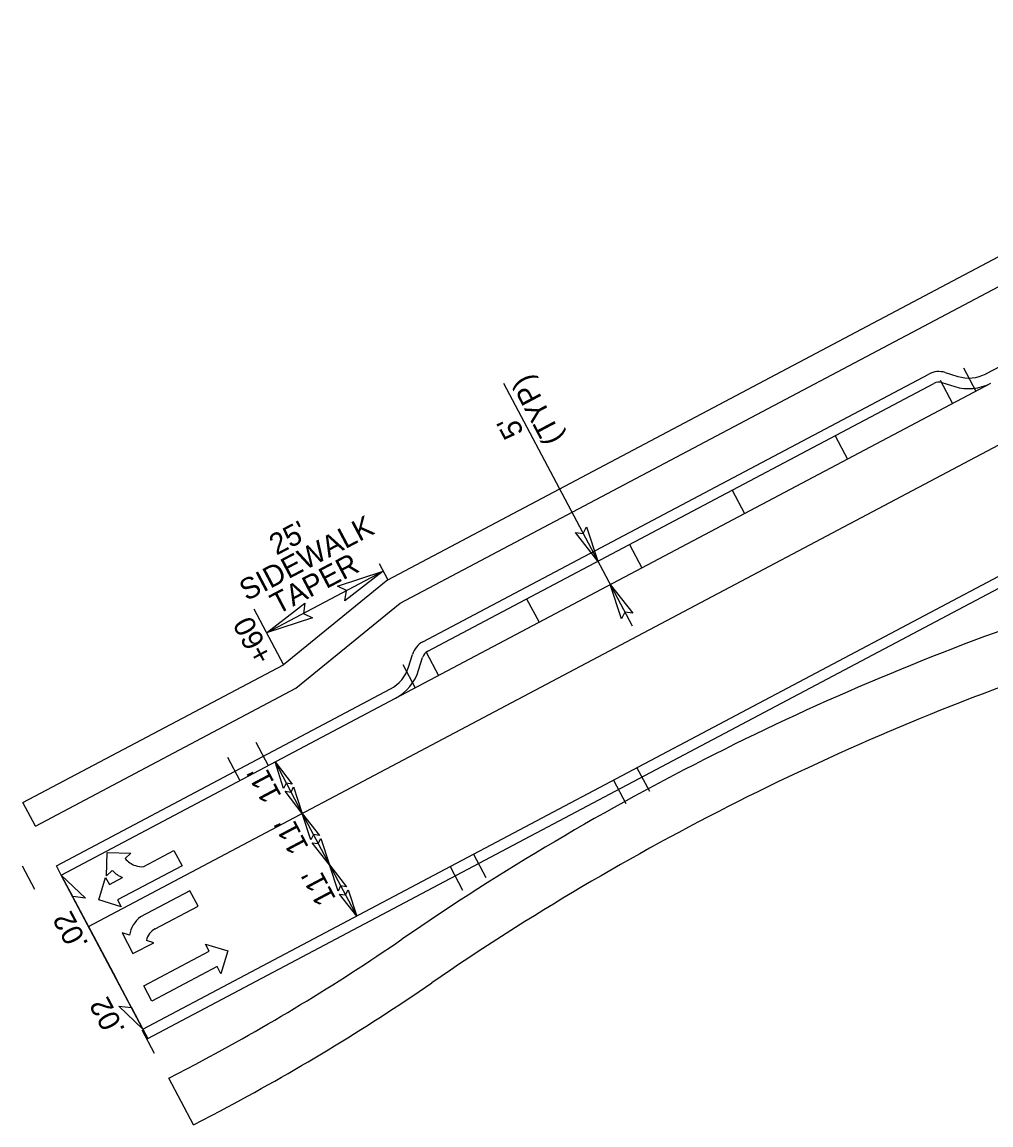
# Model space of a CAD drawing. Extents: x 1486489 to 1490134, y 497089 to 500876.
# Drawn here: x 1487826.7 to 1488009.9, y 498365 to 498573.7 of the extents above; entities that cross this region are included whole.
import ezdxf

# ---------------------------------------------------------------- set-up
doc = ezdxf.new("R2010")
doc.units = 0
for name, color, linetype in [('DEV PRELIMINARY STAMP CELL', 7, 'Continuous'), ('Gray Area Fill Shapes', 7, 'Continuous'), ('Prop Horizontal Alignment Station Label', 7, 'Continuous'), ('Scratch_Level_5', 7, 'Continuous'), ('Sheet Block Title CELL', 7, 'Continuous'), ('Sheet Border Standard 30in CELL', 7, 'Continuous'), ('Sheet Cutting Line CELL', 7, 'Continuous'), ('Sheet Plot Border Inside CELL', 7, 'Continuous'), ('Sheet Plot Border Outside CELL', 7, 'Continuous'), ('Sheet Sticker Exception Certification CELL', 7, 'Continuous'), ('Sheet Title CELL', 7, 'Continuous')]:
    doc.layers.add(name, color=color, linetype=linetype)

msp = doc.modelspace()

# ---------------------------------------------------------------- linework, layer by layer
at = {"layer": 'DEV PRELIMINARY STAMP CELL'}
for p in [(1487834.08, 498412.33), (1487849.52, 498383.17)]:
    msp.add_line(p, (1487844.38, 498392.89), dxfattribs=at)
for points in [[(1487834.08, 498412.33), (1487838.66, 498407.97), (1487836.25, 498408.25)], [(1487849.52, 498383.17), (1487844.95, 498387.53), (1487847.36, 498387.25)]]:
    msp.add_lwpolyline(points, close=True, dxfattribs=at)
at = {"layer": 'Prop Horizontal Alignment Station Label'}
for p, q in [((1487895.85, 498468.22), (1488095.16, 498573.73)), ((1487898.19, 498463.8), (1488097.5, 498569.31)), ((1487895.85, 498468.22), (1487876.09, 498452.11)), ((1487878.43, 498447.69), (1487898.19, 498463.8)), ((1487826.83, 498426.03), (1487876.09, 498452.11)), ((1487829.17, 498421.61), (1487878.43, 498447.69)), ((1487829.17, 498421.61), (1487826.83, 498426.03)), ((1487854.44, 498373.89), (1487859.51, 498376.57)), ((1487859.11, 498365.05), (1487854.44, 498373.89)), ((1487859.11, 498365.05), (1487864.18, 498367.73))]:
    msp.add_line(p, q, dxfattribs=at)
for centre, radius, start, end in [((1488184.66, 497984.09), 505, 108.9278, 124.5146), ((1488184.66, 497984.09), 495, 108.9278, 124.5146), ((1487674.7, 498725.67), 395, 297.895, 304.5146), ((1487674.7, 498725.67), 405, 297.895, 304.5146)]:
    msp.add_arc(centre, radius, start, end, dxfattribs=at)
at = {"layer": 'Scratch_Level_5'}
for p, q in [((1487850.46, 498381.4), (1488121.13, 498524.68)), ((1488008.99, 498507.18), (1488029.36, 498517.97)), ((1487902.45, 498456.44), (1487998.21, 498507.13)), ((1488001.25, 498507.42), (1488003.66, 498506.68)), ((1487899.76, 498451.68), (1487900.5, 498454.08)), ((1487833.15, 498414.1), (1487896.34, 498447.55)), ((1487834.08, 498412.33), (1487833.15, 498414.1)), ((1487849.52, 498383.17), (1487850.46, 498381.4))]:
    msp.add_line(p, q, dxfattribs=at)
for centre, radius, start, end in [((1488000.08, 498503.6), 4, 72.895, 117.895), ((1488005.72, 498513.37), 7, 252.895, 297.895), ((1487904.32, 498452.91), 4, 117.895, 162.895), ((1487893.07, 498453.74), 7, 297.895, 342.895)]:
    msp.add_arc(centre, radius, start, end, dxfattribs=at)
at = {"layer": 'Sheet Block Title CELL'}
for p, q in [((1487839.23, 498402.61), (1488109.9, 498545.89)), ((1487897.28, 498445.79), (1488009.93, 498505.42)), ((1487980.43, 498495.46), (1487982.77, 498491.04)), ((1487960.99, 498485.17), (1487963.32, 498480.75)), ((1487941.54, 498474.87), (1487943.88, 498470.45)), ((1487922.1, 498464.58), (1487924.44, 498460.16))]:
    msp.add_line(p, q, dxfattribs=at)
at = {"layer": 'Sheet Border Standard 30in CELL'}
for p, q in [((1488004.74, 498508.33), (1488007.08, 498503.91)), ((1488000.32, 498505.99), (1488002.66, 498501.57)), ((1487903.1, 498454.52), (1487905.44, 498450.11)), ((1487898.68, 498452.19), (1487901.02, 498447.77)), ((1487870.85, 498437.45), (1487873.19, 498433.03)), ((1487865.54, 498434.64), (1487867.88, 498430.22)), ((1487942.97, 498432.64), (1487945.31, 498428.22)), ((1487938.56, 498430.3), (1487940.89, 498425.88)), ((1487912.04, 498416.26), (1487914.38, 498411.84)), ((1487826.66, 498414.06), (1487829, 498409.64)), ((1487907.62, 498413.92), (1487909.96, 498409.5)), ((1487849.29, 498383.04), (1487851.63, 498378.62))]:
    msp.add_line(p, q, dxfattribs=at)
at = {"layer": 'Sheet Cutting Line CELL'}
for p, q in [((1487917.74, 498505.43), (1487942.04, 498459.52)), ((1487872.9, 498458.15), (1487894.99, 498469.84)), ((1487894.23, 498471.27), (1487895.85, 498468.22)), ((1487870.48, 498462.7), (1487876.09, 498452.11)), ((1487874.51, 498433.73), (1487879.65, 498424.01)), ((1487879.65, 498424.01), (1487884.8, 498414.29)), ((1487884.8, 498414.29), (1487889.95, 498404.57))]:
    msp.add_line(p, q, dxfattribs=at)
at = {"layer": 'Sheet Plot Border Inside CELL'}
for p, q in [((1487842.64, 498412.18), (1487842.78, 498416.61)), ((1487842.78, 498416.61), (1487847.21, 498416.47)), ((1487847.21, 498416.47), (1487846.16, 498415.46)), ((1487849.66, 498413.98), (1487855.36, 498416.99)), ((1487855.36, 498416.99), (1487856.91, 498414.08)), ((1487843.73, 498413.21), (1487842.64, 498412.18)), ((1487856.91, 498414.08), (1487844.71, 498407.62)), ((1487841.2, 498407.63), (1487842.46, 498411.86)), ((1487842.46, 498411.86), (1487843.17, 498410.54)), ((1487843.17, 498410.54), (1487845.68, 498411.87)), ((1487858.39, 498409.34), (1487849.07, 498404.41)), ((1487859.94, 498406.43), (1487858.39, 498409.34)), ((1487845.41, 498406.29), (1487841.2, 498407.63)), ((1487844.71, 498407.62), (1487845.41, 498406.29)), ((1487851.85, 498402.15), (1487859.94, 498406.43)), ((1487847, 498400.94), (1487845.58, 498401.37)), ((1487845.58, 498401.37), (1487847.6, 498397.46)), ((1487847.6, 498397.46), (1487851.6, 498399.52)), ((1487851.6, 498399.52), (1487850.18, 498399.96)), ((1487862.04, 498397.91), (1487861.34, 498399.24)), ((1487861.34, 498399.24), (1487865.57, 498397.97)), ((1487849.67, 498391.36), (1487862.04, 498397.91)), ((1487865.57, 498397.97), (1487864.28, 498393.67)), ((1487863.58, 498395), (1487851.21, 498388.45)), ((1487864.28, 498393.67), (1487863.58, 498395)), ((1487851.21, 498388.45), (1487849.67, 498391.36))]:
    msp.add_line(p, q, dxfattribs=at)
for centre, radius, start, end in [((1487849.58, 498418.29), 4.43, 219.6046, 250.4582), ((1487847.16, 498416.04), 4.43, 219.4858, 250.3644), ((1487849.08, 498416.43), 2.52, 246.9681, 283.2801), ((1487852.19, 498400.2), 5.25, 126.571, 171.8827), ((1487853.37, 498399.26), 3.28, 117.895, 167.5531)]:
    msp.add_arc(centre, radius, start, end, dxfattribs=at)
at = {"layer": 'Sheet Plot Border Outside CELL'}
for points in [[(1487933.45, 498478.23), (1487935.58, 498471.72), (1487931.35, 498477.16), (1487932.81, 498476.96)], [(1487886.31, 498467), (1487894.99, 498469.84), (1487887.74, 498464.2), (1487888.01, 498466.15)], [(1487940.05, 498460.79), (1487937.92, 498467.3), (1487942.16, 498461.86), (1487940.69, 498462.06)], [(1487881.58, 498460.99), (1487872.9, 498458.15), (1487880.15, 498463.8), (1487879.88, 498461.84)], [(1487876.14, 498428.74), (1487874.51, 498433.73), (1487877.75, 498429.56), (1487876.63, 498429.72)], [(1487878.02, 498429), (1487879.65, 498424.01), (1487876.41, 498428.18), (1487877.53, 498428.02)], [(1487881.29, 498419.02), (1487879.65, 498424.01), (1487882.9, 498419.84), (1487881.78, 498419.99)], [(1487883.17, 498419.28), (1487884.8, 498414.29), (1487881.55, 498418.46), (1487882.67, 498418.3)], [(1487886.43, 498409.3), (1487884.8, 498414.29), (1487888.05, 498410.12), (1487886.92, 498410.27)], [(1487888.31, 498409.56), (1487889.95, 498404.57), (1487886.7, 498408.73), (1487887.82, 498408.58)]]:
    msp.add_lwpolyline(points, close=True, dxfattribs=at)
at = {"layer": 'Sheet Sticker Exception Certification CELL'}
for p, q in [((1487849.52, 498383.17), (1488120.19, 498526.45)), ((1487903.39, 498454.68), (1487999.14, 498505.36)), ((1488000.66, 498505.51), (1488003.07, 498504.77)), ((1487901.67, 498451.09), (1487902.41, 498453.5)), ((1487834.08, 498412.33), (1487897.28, 498445.79)), ((1487849.52, 498383.17), (1487834.08, 498412.33))]:
    msp.add_line(p, q, dxfattribs=at)
for centre, radius, start, end in [((1488000.08, 498503.6), 2, 72.895, 117.895), ((1488005.72, 498513.37), 9, 252.895, 297.895), ((1487904.32, 498452.91), 2, 117.895, 162.895), ((1487893.07, 498453.74), 9, 297.895, 342.895)]:
    msp.add_arc(centre, radius, start, end, dxfattribs=at)

# ---------------------------------------------------------------- texts
at = {"layer": 'Gray Area Fill Shapes'}
for p in [(1487839.31, 498399.3), (1487846.25, 498383.08)]:
    msp.add_text('.02', height=4, rotation=117.895, dxfattribs=at).set_placement(p)
at = {"layer": 'Sheet Title CELL'}
for s, rotation, p in [('(TYP)', 117.895, (1487929.08, 498495)), ("5'", 117.895, (1487921.67, 498496.17)), ('SIDEWALK', 27.8351, (1487869.13, 498464.12)), ("25'", 27.8351, (1487874.78, 498472.76)), ('TAPER', 27.8351, (1487874.99, 498461.56)), ('+60', 117.895, (1487874.17, 498453.63)), ("11'", 117.895, (1487875.83, 498427.31)), ("11'", 117.895, (1487880.97, 498417.59)), ("11'", 117.895, (1487886.12, 498407.86))]:
    msp.add_text(s, height=4, rotation=rotation, dxfattribs=at).set_placement(p)

doc.saveas('drawing.dxf')
